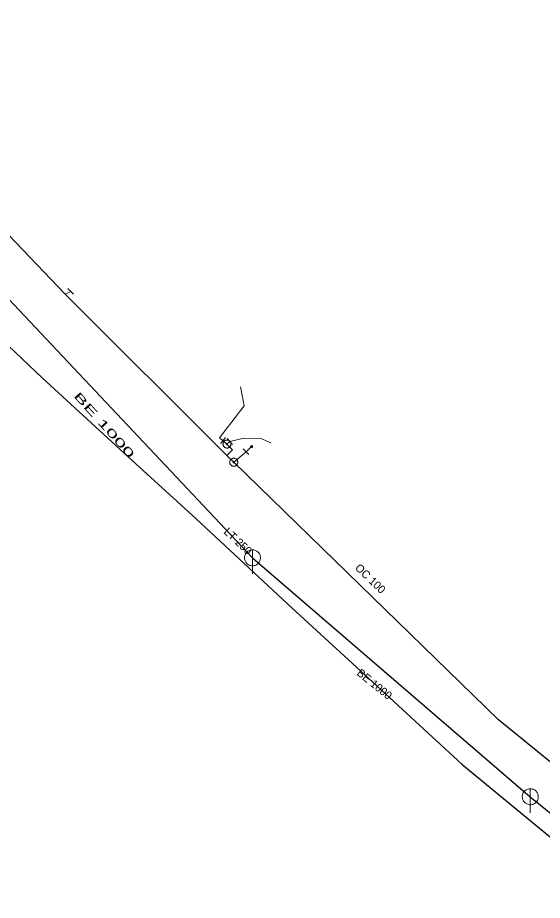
# Model space of a CAD drawing. Extents: x -807203 to -805207, y -993656 to -992505.
# Drawn here: x -806503.5 to -806438, y -992895 to -992784.7 of the extents above; entities that cross this region are included whole.
import ezdxf

# ---------------------------------------------------------------- set-up
doc = ezdxf.new("R2010")
doc.units = 0
doc.header["$LTSCALE"] = 0.4
for name, color, linetype, lineweight in [('1', 7, 'Continuous', 13), ('13', 7, 'Continuous', 13), ('14', 7, 'Continuous', 25), ('17', 7, 'Continuous', 25), ('22', 7, 'Continuous', 13), ('34', 7, 'Continuous', 13), ('47', 7, 'Continuous', 13), ('9', 7, 'Continuous', 13)]:
    doc.layers.add(name, color=color, linetype=linetype, lineweight=lineweight)

msp = doc.modelspace()

# ---------------------------------------------------------------- linework, layer by layer
at = {"layer": '13'}
for points in [[(-806477.891, -992837.549), (-806478.33, -992837.194), (-806475.237, -992833.223), (-806475.697, -992830.862)], [(-806477.034, -992837.674), (-806475.299, -992837.256), (-806473.168, -992837.277), (-806471.914, -992837.821)]]:
    msp.add_lwpolyline(points, dxfattribs=at)
at = {"layer": '14'}
for p, q in [((-806510.489, -992813.739), (-806474.199, -992852.199)), ((-806474.199, -992852.199), (-806439.491, -992882.042))]:
    msp.add_line(p, q, dxfattribs=at)
at = {"layer": '14', "lineweight": 13}
for p, q in [((-806497.604, -992819.259), (-806496.915, -992818.914)), ((-806477.389, -992837.988), (-806477.891, -992837.549))]:
    msp.add_line(p, q, dxfattribs=at)
for points in [[(-806477.405, -992839.403), (-806476.7, -992838.698), (-806477.389, -992837.988), (-806477.034, -992837.674)], [(-806476.543, -992840.262), (-806474.993, -992838.942), (-806474.305, -992838.311)]]:
    msp.add_lwpolyline(points, dxfattribs=at)
at = {"layer": '14'}
msp.add_lwpolyline([(-806439.491, -992882.042), (-806390.48, -992921.449), (-806366.285, -992941.529), (-806350.28, -992945.949), (-806336.559, -992959.469), (-806296.91, -993006.629), (-806254.43, -993051.92)], dxfattribs=at)
at = {"layer": '17'}
for points in [[(-806713.738, -992548.818), (-806700.103, -992562.285), (-806693.842, -992569.743), (-806679.548, -992587.69), (-806626.239, -992660.002), (-806578.693, -992725.552), (-806563.455, -992747.297), (-806547.484, -992770.088), (-806530.704, -992784.989), (-806525.097, -992790.538), (-806497.604, -992819.259), (-806477.405, -992839.403), (-806476.543, -992840.262)], [(-806521.443, -992807.149), (-806519.338, -992810.368), (-806510.309, -992820.324), (-806509.868, -992820.798), (-806504.706, -992825.727), (-806500.491, -992829.715), (-806490.227, -992839.136), (-806481.238, -992847.311), (-806469.245, -992858.467), (-806459.171, -992867.71), (-806448.037, -992877.98), (-806436.941, -992887.123)], [(-806433.161, -992880.802), (-806443.471, -992872.44), (-806476.543, -992840.262)]]:
    msp.add_lwpolyline(points, dxfattribs=at)
at = {"layer": '22'}
for p, q in [((-806474.199, -992854.199), (-806474.198, -992851.199)), ((-806439.491, -992884.042), (-806439.49, -992881.042))]:
    msp.add_line(p, q, dxfattribs=at)
for points in [[(-806473.199, -992852.199), (-806473.204, -992852.09), (-806473.222, -992851.982), (-806473.252, -992851.876), (-806473.292, -992851.775), (-806473.344, -992851.678), (-806473.406, -992851.588), (-806473.478, -992851.505), (-806473.558, -992851.431), (-806473.646, -992851.365), (-806473.74, -992851.31), (-806473.84, -992851.265), (-806473.945, -992851.232), (-806474.052, -992851.21), (-806474.161, -992851.2), (-806474.271, -992851.202), (-806474.379, -992851.216), (-806474.486, -992851.241), (-806474.589, -992851.278), (-806474.687, -992851.327), (-806474.779, -992851.385), (-806474.865, -992851.454), (-806474.942, -992851.531), (-806475.011, -992851.617), (-806475.07, -992851.709), (-806475.118, -992851.807), (-806475.155, -992851.91), (-806475.181, -992852.017), (-806475.195, -992852.125), (-806475.198, -992852.235), (-806475.188, -992852.344), (-806475.167, -992852.451), (-806475.133, -992852.555), (-806475.089, -992852.655), (-806475.034, -992852.75), (-806474.968, -992852.838), (-806474.894, -992852.918), (-806474.811, -992852.99), (-806474.721, -992853.052), (-806474.625, -992853.104), (-806474.523, -992853.145), (-806474.418, -992853.175), (-806474.31, -992853.193), (-806474.2, -992853.199), (-806474.091, -992853.193), (-806473.983, -992853.175), (-806473.878, -992853.146), (-806473.776, -992853.105), (-806473.679, -992853.053), (-806473.589, -992852.991), (-806473.506, -992852.92), (-806473.431, -992852.84), (-806473.366, -992852.752), (-806473.31, -992852.658), (-806473.266, -992852.558), (-806473.232, -992852.454), (-806473.21, -992852.346), (-806473.2, -992852.237)], [(-806438.491, -992882.042), (-806438.496, -992881.933), (-806438.514, -992881.825), (-806438.544, -992881.719), (-806438.584, -992881.618), (-806438.636, -992881.521), (-806438.698, -992881.431), (-806438.77, -992881.348), (-806438.85, -992881.274), (-806438.938, -992881.208), (-806439.032, -992881.153), (-806439.132, -992881.108), (-806439.237, -992881.075), (-806439.344, -992881.053), (-806439.453, -992881.043), (-806439.563, -992881.045), (-806439.671, -992881.059), (-806439.778, -992881.084), (-806439.881, -992881.121), (-806439.979, -992881.17), (-806440.071, -992881.228), (-806440.157, -992881.297), (-806440.234, -992881.374), (-806440.303, -992881.46), (-806440.362, -992881.552), (-806440.41, -992881.65), (-806440.447, -992881.753), (-806440.473, -992881.86), (-806440.487, -992881.968), (-806440.49, -992882.078), (-806440.48, -992882.187), (-806440.459, -992882.294), (-806440.425, -992882.398), (-806440.381, -992882.498), (-806440.326, -992882.593), (-806440.26, -992882.681), (-806440.186, -992882.761), (-806440.103, -992882.833), (-806440.013, -992882.895), (-806439.917, -992882.947), (-806439.815, -992882.988), (-806439.71, -992883.018), (-806439.602, -992883.036), (-806439.492, -992883.042), (-806439.383, -992883.036), (-806439.275, -992883.018), (-806439.17, -992882.989), (-806439.068, -992882.948), (-806438.971, -992882.896), (-806438.881, -992882.834), (-806438.798, -992882.763), (-806438.723, -992882.683), (-806438.658, -992882.595), (-806438.602, -992882.501), (-806438.558, -992882.401), (-806438.524, -992882.297), (-806438.502, -992882.189), (-806438.492, -992882.08)]]:
    msp.add_lwpolyline(points, close=True, dxfattribs=at)
at = {"layer": '34'}
for p, q in [((-806497.268, -992818.56), (-806496.561, -992819.267)), ((-806478.219, -992837.925), (-806477.561, -992837.173)), ((-806477.365, -992837.299), (-806476.703, -992838.049)), ((-806475.348, -992838.59), (-806474.638, -992839.294))]:
    msp.add_line(p, q, dxfattribs=at)
at = {"layer": '47'}
for points in [[(-806477.737, -992837.629), (-806477.772, -992837.667), (-806477.804, -992837.709), (-806477.83, -992837.754), (-806477.852, -992837.801), (-806477.869, -992837.851), (-806477.881, -992837.902), (-806477.887, -992837.954), (-806477.887, -992838.006), (-806477.883, -992838.058), (-806477.873, -992838.11), (-806477.858, -992838.16), (-806477.837, -992838.208), (-806477.812, -992838.253), (-806477.781, -992838.296), (-806477.747, -992838.336), (-806477.709, -992838.371), (-806477.667, -992838.403), (-806477.621, -992838.43), (-806477.575, -992838.451), (-806477.525, -992838.468), (-806477.474, -992838.48), (-806477.421, -992838.486), (-806477.369, -992838.487), (-806477.317, -992838.483), (-806477.266, -992838.472), (-806477.216, -992838.457), (-806477.167, -992838.436), (-806477.123, -992838.411), (-806477.08, -992838.38), (-806477.04, -992838.346), (-806477.005, -992838.308), (-806476.973, -992838.266), (-806476.946, -992838.221), (-806476.925, -992838.174), (-806476.908, -992838.124), (-806476.895, -992838.073), (-806476.889, -992838.021), (-806476.888, -992837.969), (-806476.893, -992837.916), (-806476.904, -992837.865), (-806476.919, -992837.815), (-806476.939, -992837.767), (-806476.965, -992837.722), (-806476.996, -992837.679), (-806477.03, -992837.639), (-806477.068, -992837.604), (-806477.11, -992837.572), (-806477.154, -992837.545), (-806477.202, -992837.524), (-806477.252, -992837.507), (-806477.303, -992837.494), (-806477.354, -992837.489), (-806477.407, -992837.488), (-806477.459, -992837.493), (-806477.511, -992837.503), (-806477.561, -992837.518), (-806477.608, -992837.539), (-806477.654, -992837.564), (-806477.697, -992837.595)], [(-806477.446, -992837.929), (-806477.452, -992837.935), (-806477.456, -992837.942), (-806477.461, -992837.949), (-806477.464, -992837.957), (-806477.467, -992837.965), (-806477.469, -992837.974), (-806477.47, -992837.982), (-806477.471, -992837.991), (-806477.469, -992837.999), (-806477.468, -992838.008), (-806477.465, -992838.016), (-806477.462, -992838.024), (-806477.458, -992838.031), (-806477.454, -992838.038), (-806477.447, -992838.045), (-806477.441, -992838.051), (-806477.434, -992838.055), (-806477.427, -992838.06), (-806477.419, -992838.063), (-806477.411, -992838.066), (-806477.402, -992838.068), (-806477.394, -992838.069), (-806477.385, -992838.07), (-806477.376, -992838.069), (-806477.368, -992838.067), (-806477.36, -992838.064), (-806477.352, -992838.061), (-806477.345, -992838.057), (-806477.338, -992838.053), (-806477.331, -992838.046), (-806477.325, -992838.04), (-806477.321, -992838.033), (-806477.316, -992838.026), (-806477.313, -992838.018), (-806477.31, -992838.01), (-806477.307, -992838.002), (-806477.307, -992837.993), (-806477.306, -992837.984), (-806477.307, -992837.975), (-806477.309, -992837.967), (-806477.312, -992837.959), (-806477.315, -992837.951), (-806477.319, -992837.944), (-806477.323, -992837.937), (-806477.33, -992837.93), (-806477.336, -992837.924), (-806477.343, -992837.92), (-806477.35, -992837.915), (-806477.358, -992837.912), (-806477.366, -992837.909), (-806477.374, -992837.906), (-806477.383, -992837.906), (-806477.392, -992837.905), (-806477.4, -992837.907), (-806477.409, -992837.908), (-806477.417, -992837.911), (-806477.425, -992837.914), (-806477.432, -992837.918), (-806477.439, -992837.922)], [(-806476.165, -992840.59), (-806476.133, -992840.548), (-806476.105, -992840.504), (-806476.083, -992840.457), (-806476.064, -992840.408), (-806476.052, -992840.357), (-806476.045, -992840.305), (-806476.043, -992840.253), (-806476.047, -992840.201), (-806476.056, -992840.15), (-806476.07, -992840.099), (-806476.089, -992840.05), (-806476.115, -992840.004), (-806476.143, -992839.961), (-806476.177, -992839.921), (-806476.214, -992839.884), (-806476.256, -992839.852), (-806476.3, -992839.824), (-806476.348, -992839.801), (-806476.396, -992839.783), (-806476.447, -992839.771), (-806476.499, -992839.764), (-806476.552, -992839.762), (-806476.604, -992839.765), (-806476.655, -992839.774), (-806476.705, -992839.789), (-806476.754, -992839.808), (-806476.801, -992839.833), (-806476.843, -992839.862), (-806476.883, -992839.896), (-806476.92, -992839.933), (-806476.952, -992839.975), (-806476.98, -992840.019), (-806477.003, -992840.066), (-806477.021, -992840.115), (-806477.033, -992840.166), (-806477.041, -992840.218), (-806477.043, -992840.27), (-806477.039, -992840.322), (-806477.03, -992840.374), (-806477.015, -992840.424), (-806476.996, -992840.473), (-806476.972, -992840.519), (-806476.942, -992840.562), (-806476.908, -992840.602), (-806476.871, -992840.639), (-806476.829, -992840.671), (-806476.785, -992840.699), (-806476.739, -992840.722), (-806476.689, -992840.74), (-806476.638, -992840.752), (-806476.586, -992840.76), (-806476.535, -992840.761), (-806476.482, -992840.758), (-806476.431, -992840.748), (-806476.38, -992840.734), (-806476.331, -992840.715), (-806476.286, -992840.69), (-806476.242, -992840.661), (-806476.202, -992840.627)], [(-806476.481, -992840.315), (-806476.475, -992840.309), (-806476.471, -992840.301), (-806476.467, -992840.294), (-806476.464, -992840.286), (-806476.462, -992840.277), (-806476.461, -992840.269), (-806476.46, -992840.26), (-806476.461, -992840.252), (-806476.463, -992840.243), (-806476.465, -992840.235), (-806476.468, -992840.227), (-806476.472, -992840.219), (-806476.477, -992840.212), (-806476.482, -992840.206), (-806476.489, -992840.2), (-806476.495, -992840.194), (-806476.503, -992840.19), (-806476.51, -992840.186), (-806476.518, -992840.183), (-806476.527, -992840.181), (-806476.535, -992840.18), (-806476.544, -992840.179), (-806476.552, -992840.18), (-806476.562, -992840.181), (-806476.569, -992840.184), (-806476.577, -992840.187), (-806476.585, -992840.191), (-806476.592, -992840.196), (-806476.598, -992840.201), (-806476.604, -992840.208), (-806476.61, -992840.214), (-806476.614, -992840.222), (-806476.618, -992840.229), (-806476.621, -992840.237), (-806476.623, -992840.246), (-806476.625, -992840.254), (-806476.625, -992840.263), (-806476.624, -992840.271), (-806476.623, -992840.281), (-806476.62, -992840.288), (-806476.617, -992840.296), (-806476.613, -992840.304), (-806476.608, -992840.311), (-806476.603, -992840.317), (-806476.596, -992840.323), (-806476.59, -992840.329), (-806476.582, -992840.333), (-806476.575, -992840.337), (-806476.567, -992840.34), (-806476.558, -992840.342), (-806476.55, -992840.344), (-806476.541, -992840.344), (-806476.533, -992840.343), (-806476.524, -992840.341), (-806476.516, -992840.339), (-806476.508, -992840.336), (-806476.5, -992840.332), (-806476.493, -992840.327), (-806476.487, -992840.322)]]:
    msp.add_lwpolyline(points, close=True, dxfattribs=at)
at = {"layer": '9'}
for points in [[(-806474.431, -992838.311), (-806474.431, -992838.324), (-806474.429, -992838.337), (-806474.426, -992838.35), (-806474.421, -992838.362), (-806474.415, -992838.374), (-806474.408, -992838.385), (-806474.4, -992838.395), (-806474.39, -992838.405), (-806474.38, -992838.413), (-806474.369, -992838.42), (-806474.357, -992838.426), (-806474.345, -992838.431), (-806474.332, -992838.434), (-806474.319, -992838.436), (-806474.306, -992838.438), (-806474.293, -992838.437), (-806474.28, -992838.435), (-806474.267, -992838.432), (-806474.255, -992838.427), (-806474.243, -992838.421), (-806474.232, -992838.414), (-806474.222, -992838.406), (-806474.212, -992838.396), (-806474.204, -992838.386), (-806474.197, -992838.375), (-806474.191, -992838.363), (-806474.186, -992838.351), (-806474.183, -992838.338), (-806474.181, -992838.325), (-806474.179, -992838.312), (-806474.18, -992838.299), (-806474.182, -992838.286), (-806474.185, -992838.273), (-806474.19, -992838.261), (-806474.196, -992838.249), (-806474.203, -992838.238), (-806474.211, -992838.228), (-806474.221, -992838.218), (-806474.231, -992838.21), (-806474.242, -992838.203), (-806474.254, -992838.197), (-806474.266, -992838.192), (-806474.279, -992838.189), (-806474.292, -992838.187), (-806474.305, -992838.186), (-806474.318, -992838.186), (-806474.331, -992838.188), (-806474.344, -992838.191), (-806474.356, -992838.196), (-806474.368, -992838.202), (-806474.379, -992838.209), (-806474.389, -992838.217), (-806474.399, -992838.227), (-806474.407, -992838.237), (-806474.414, -992838.248), (-806474.42, -992838.26), (-806474.425, -992838.272), (-806474.428, -992838.285), (-806474.43, -992838.298)], [(-806474.411, -992838.311), (-806474.412, -992838.322), (-806474.41, -992838.333), (-806474.407, -992838.344), (-806474.403, -992838.354), (-806474.398, -992838.364), (-806474.392, -992838.373), (-806474.385, -992838.382), (-806474.377, -992838.39), (-806474.368, -992838.397), (-806474.359, -992838.403), (-806474.349, -992838.408), (-806474.339, -992838.412), (-806474.328, -992838.415), (-806474.317, -992838.418), (-806474.306, -992838.418), (-806474.295, -992838.418), (-806474.284, -992838.416), (-806474.273, -992838.413), (-806474.263, -992838.409), (-806474.253, -992838.404), (-806474.244, -992838.398), (-806474.235, -992838.391), (-806474.227, -992838.383), (-806474.22, -992838.374), (-806474.214, -992838.365), (-806474.209, -992838.355), (-806474.205, -992838.345), (-806474.202, -992838.334), (-806474.2, -992838.323), (-806474.199, -992838.312), (-806474.199, -992838.301), (-806474.201, -992838.29), (-806474.204, -992838.279), (-806474.208, -992838.269), (-806474.213, -992838.259), (-806474.219, -992838.25), (-806474.226, -992838.241), (-806474.234, -992838.233), (-806474.243, -992838.226), (-806474.252, -992838.22), (-806474.262, -992838.215), (-806474.272, -992838.211), (-806474.283, -992838.208), (-806474.294, -992838.206), (-806474.305, -992838.206), (-806474.316, -992838.205), (-806474.327, -992838.207), (-806474.338, -992838.21), (-806474.348, -992838.214), (-806474.358, -992838.219), (-806474.367, -992838.225), (-806474.376, -992838.232), (-806474.384, -992838.24), (-806474.391, -992838.249), (-806474.397, -992838.258), (-806474.402, -992838.268), (-806474.406, -992838.278), (-806474.409, -992838.289), (-806474.411, -992838.3)], [(-806474.392, -992838.311), (-806474.392, -992838.32), (-806474.391, -992838.329), (-806474.388, -992838.338), (-806474.385, -992838.346), (-806474.381, -992838.354), (-806474.376, -992838.362), (-806474.37, -992838.369), (-806474.364, -992838.375), (-806474.357, -992838.381), (-806474.349, -992838.386), (-806474.341, -992838.39), (-806474.333, -992838.393), (-806474.324, -992838.396), (-806474.315, -992838.397), (-806474.306, -992838.399), (-806474.297, -992838.398), (-806474.288, -992838.397), (-806474.279, -992838.394), (-806474.271, -992838.391), (-806474.263, -992838.387), (-806474.255, -992838.382), (-806474.248, -992838.376), (-806474.242, -992838.37), (-806474.236, -992838.363), (-806474.231, -992838.355), (-806474.227, -992838.347), (-806474.224, -992838.339), (-806474.221, -992838.33), (-806474.22, -992838.321), (-806474.218, -992838.312), (-806474.219, -992838.303), (-806474.22, -992838.294), (-806474.223, -992838.285), (-806474.226, -992838.277), (-806474.23, -992838.269), (-806474.235, -992838.261), (-806474.241, -992838.254), (-806474.247, -992838.248), (-806474.254, -992838.242), (-806474.262, -992838.237), (-806474.27, -992838.233), (-806474.278, -992838.23), (-806474.287, -992838.227), (-806474.296, -992838.226), (-806474.305, -992838.225), (-806474.314, -992838.225), (-806474.323, -992838.226), (-806474.332, -992838.229), (-806474.34, -992838.232), (-806474.348, -992838.236), (-806474.356, -992838.241), (-806474.363, -992838.247), (-806474.369, -992838.253), (-806474.375, -992838.26), (-806474.38, -992838.268), (-806474.384, -992838.276), (-806474.387, -992838.284), (-806474.39, -992838.293), (-806474.391, -992838.302)], [(-806474.372, -992838.311), (-806474.372, -992838.318), (-806474.371, -992838.325), (-806474.37, -992838.332), (-806474.367, -992838.338), (-806474.364, -992838.344), (-806474.36, -992838.35), (-806474.356, -992838.356), (-806474.351, -992838.361), (-806474.345, -992838.365), (-806474.339, -992838.369), (-806474.333, -992838.372), (-806474.327, -992838.375), (-806474.32, -992838.376), (-806474.313, -992838.379), (-806474.306, -992838.379), (-806474.299, -992838.379), (-806474.292, -992838.377), (-806474.285, -992838.376), (-806474.279, -992838.373), (-806474.272, -992838.37), (-806474.267, -992838.366), (-806474.261, -992838.362), (-806474.256, -992838.357), (-806474.252, -992838.351), (-806474.248, -992838.345), (-806474.245, -992838.339), (-806474.242, -992838.333), (-806474.24, -992838.326), (-806474.239, -992838.319), (-806474.238, -992838.312), (-806474.238, -992838.305), (-806474.239, -992838.298), (-806474.241, -992838.291), (-806474.244, -992838.285), (-806474.247, -992838.278), (-806474.251, -992838.273), (-806474.255, -992838.267), (-806474.26, -992838.262), (-806474.266, -992838.258), (-806474.271, -992838.254), (-806474.278, -992838.251), (-806474.284, -992838.248), (-806474.291, -992838.246), (-806474.298, -992838.245), (-806474.305, -992838.245), (-806474.312, -992838.245), (-806474.319, -992838.245), (-806474.326, -992838.247), (-806474.332, -992838.25), (-806474.338, -992838.253), (-806474.344, -992838.257), (-806474.35, -992838.261), (-806474.355, -992838.266), (-806474.359, -992838.272), (-806474.363, -992838.277), (-806474.366, -992838.284), (-806474.369, -992838.29), (-806474.37, -992838.297), (-806474.372, -992838.304)], [(-806474.352, -992838.311), (-806474.352, -992838.316), (-806474.352, -992838.321), (-806474.351, -992838.326), (-806474.349, -992838.33), (-806474.347, -992838.335), (-806474.344, -992838.339), (-806474.341, -992838.342), (-806474.337, -992838.346), (-806474.334, -992838.349), (-806474.33, -992838.352), (-806474.325, -992838.354), (-806474.321, -992838.356), (-806474.316, -992838.357), (-806474.311, -992838.359), (-806474.306, -992838.359), (-806474.301, -992838.359), (-806474.296, -992838.358), (-806474.291, -992838.357), (-806474.287, -992838.355), (-806474.282, -992838.353), (-806474.278, -992838.35), (-806474.274, -992838.347), (-806474.271, -992838.343), (-806474.268, -992838.34), (-806474.265, -992838.336), (-806474.263, -992838.331), (-806474.261, -992838.327), (-806474.26, -992838.322), (-806474.259, -992838.317), (-806474.258, -992838.312), (-806474.258, -992838.307), (-806474.259, -992838.302), (-806474.26, -992838.297), (-806474.262, -992838.293), (-806474.264, -992838.288), (-806474.267, -992838.284), (-806474.27, -992838.28), (-806474.273, -992838.277), (-806474.277, -992838.274), (-806474.281, -992838.271), (-806474.286, -992838.269), (-806474.29, -992838.267), (-806474.295, -992838.266), (-806474.3, -992838.265), (-806474.305, -992838.265), (-806474.31, -992838.265), (-806474.315, -992838.266), (-806474.32, -992838.266), (-806474.324, -992838.268), (-806474.329, -992838.27), (-806474.333, -992838.273), (-806474.336, -992838.276), (-806474.34, -992838.279), (-806474.343, -992838.283), (-806474.346, -992838.287), (-806474.348, -992838.292), (-806474.35, -992838.296), (-806474.351, -992838.301), (-806474.352, -992838.306)], [(-806474.332, -992838.311), (-806474.332, -992838.314), (-806474.333, -992838.317), (-806474.332, -992838.319), (-806474.331, -992838.322), (-806474.33, -992838.325), (-806474.328, -992838.327), (-806474.326, -992838.329), (-806474.324, -992838.331), (-806474.322, -992838.333), (-806474.32, -992838.335), (-806474.317, -992838.337), (-806474.314, -992838.338), (-806474.312, -992838.338), (-806474.309, -992838.339), (-806474.306, -992838.339), (-806474.303, -992838.339), (-806474.3, -992838.339), (-806474.297, -992838.338), (-806474.295, -992838.337), (-806474.292, -992838.336), (-806474.29, -992838.334), (-806474.287, -992838.332), (-806474.285, -992838.33), (-806474.284, -992838.328), (-806474.282, -992838.326), (-806474.281, -992838.323), (-806474.279, -992838.32), (-806474.279, -992838.318), (-806474.278, -992838.315), (-806474.277, -992838.312), (-806474.278, -992838.309), (-806474.278, -992838.306), (-806474.279, -992838.303), (-806474.28, -992838.301), (-806474.281, -992838.298), (-806474.283, -992838.296), (-806474.284, -992838.293), (-806474.286, -992838.291), (-806474.289, -992838.29), (-806474.291, -992838.288), (-806474.294, -992838.287), (-806474.296, -992838.286), (-806474.299, -992838.285), (-806474.302, -992838.285), (-806474.305, -992838.284), (-806474.308, -992838.285), (-806474.311, -992838.284), (-806474.313, -992838.286), (-806474.316, -992838.286), (-806474.319, -992838.287), (-806474.321, -992838.289), (-806474.323, -992838.29), (-806474.325, -992838.292), (-806474.327, -992838.295), (-806474.329, -992838.297), (-806474.33, -992838.3), (-806474.331, -992838.302), (-806474.332, -992838.305), (-806474.332, -992838.308)], [(-806474.313, -992838.311), (-806474.313, -992838.313), (-806474.313, -992838.313), (-806474.312, -992838.313), (-806474.312, -992838.315), (-806474.313, -992838.316), (-806474.311, -992838.316), (-806474.311, -992838.316), (-806474.311, -992838.318), (-806474.311, -992838.318), (-806474.31, -992838.319), (-806474.308, -992838.319), (-806474.308, -992838.319), (-806474.308, -992838.32), (-806474.306, -992838.32), (-806474.306, -992838.32), (-806474.305, -992838.32), (-806474.304, -992838.32), (-806474.304, -992838.319), (-806474.303, -992838.319), (-806474.301, -992838.319), (-806474.301, -992838.318), (-806474.301, -992838.318), (-806474.3, -992838.317), (-806474.3, -992838.317), (-806474.298, -992838.316), (-806474.298, -992838.315), (-806474.297, -992838.314), (-806474.297, -992838.314), (-806474.297, -992838.313), (-806474.297, -992838.312), (-806474.297, -992838.311), (-806474.297, -992838.31), (-806474.297, -992838.31), (-806474.298, -992838.309), (-806474.298, -992838.308), (-806474.299, -992838.307), (-806474.299, -992838.307), (-806474.3, -992838.306), (-806474.3, -992838.306), (-806474.301, -992838.305), (-806474.302, -992838.305), (-806474.303, -992838.304), (-806474.303, -992838.304), (-806474.304, -992838.304), (-806474.305, -992838.304), (-806474.306, -992838.304), (-806474.307, -992838.304), (-806474.307, -992838.304), (-806474.308, -992838.305), (-806474.309, -992838.304), (-806474.31, -992838.306), (-806474.31, -992838.306), (-806474.311, -992838.306), (-806474.311, -992838.306), (-806474.312, -992838.308), (-806474.312, -992838.309), (-806474.312, -992838.31), (-806474.313, -992838.31), (-806474.313, -992838.311)]]:
    msp.add_lwpolyline(points, close=True, dxfattribs=at)

# ---------------------------------------------------------------- texts
at = {"layer": '1', "width": 2.05}
msp.add_text('BE 1000 ', height=1, rotation=312, dxfattribs=at).set_placement((-806496.617, -992832.025))
at = {"layer": '1'}
for s, rotation, p in [('LT 250', 317, (-806477.881, -992849.064)), ('OC 100', 316, (-806461.469, -992853.552)), ('BE 1000 ', 321, (-806461.262, -992866.754))]:
    msp.add_text(s, height=1, rotation=rotation, dxfattribs=at).set_placement(p)

doc.saveas('drawing.dxf')
